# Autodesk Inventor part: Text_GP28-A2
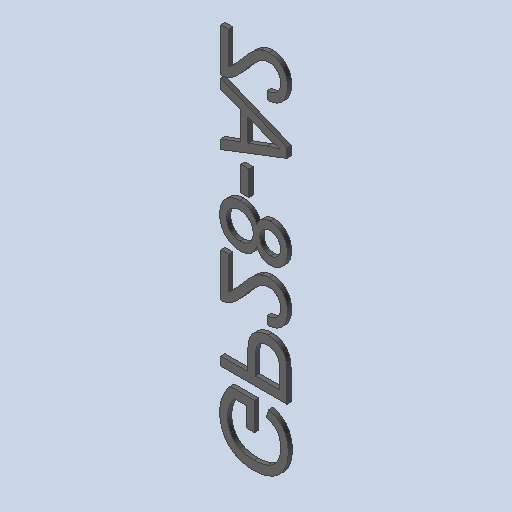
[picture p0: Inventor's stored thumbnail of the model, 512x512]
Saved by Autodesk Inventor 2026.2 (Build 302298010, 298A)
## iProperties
Created: 2026-10
Part Number: Text_GP28-A2
Material: Générique
Document SubType Name: Modeling
Designer: mel
Density: 1 g/cm^3
Appearance: Par défaut
Author: mel
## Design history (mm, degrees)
feature "Base1"
feature "Base2"
feature "Base3"
feature "Base4"
feature "Base5"
feature "Base6"
feature "Base7"
node "Solide1"
node "Solide2"
node "Solide3"
node "Solide4"
node "Solide5"
node "Solide6"
node "Solide7"
